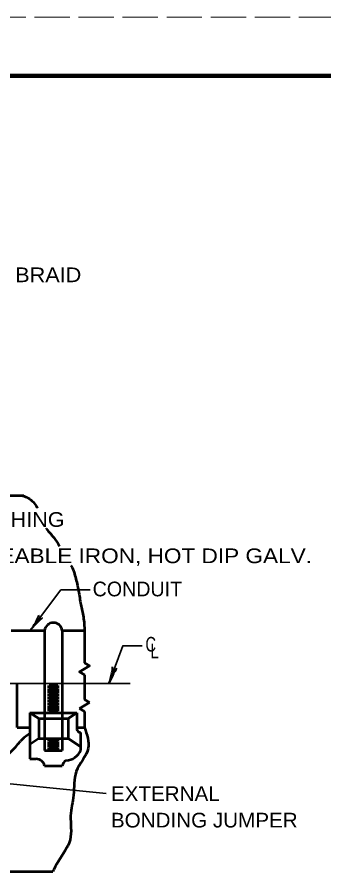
# Model space of a CAD drawing. Extents: x -1 to 679, y 0 to 440.
# Drawn here: x 295.7 to 347.9, y 293.3 to 439.8 of the extents above; entities that cross this region are included whole.
import ezdxf

# ---------------------------------------------------------------- set-up
doc = ezdxf.new("R2010")
doc.units = 0
doc.linetypes.add('LONG_DASHED', pattern=[7.5, 6, -1.5])
doc.layers.add('1', color=7, linetype='Continuous', lineweight=35)
doc.layers.add('61', color=7, linetype='Continuous', lineweight=35)

msp = doc.modelspace()

# ---------------------------------------------------------------- linework, layer by layer
at = {"layer": '1', "lineweight": 53}
for p, q in [((276.934, 358.376), (296.784, 358.376)), ((294.627, 335.376), (300.343, 335.376)), ((300.343, 335.376), (300.343, 314.992)), ((303.343, 335.376), (303.343, 314.992)), ((303.343, 335.376), (307.127, 335.376)), ((307.127, 335.376), (307.127, 329.876)), ((307.127, 327.876), (307.127, 323.626)), ((295.684, 318.876), (295.684, 326.376)), ((300.843, 325.876), (302.843, 325.876)), ((300.843, 325.376), (302.843, 325.376)), ((301.093, 326.126), (302.593, 326.126)), ((301.093, 325.626), (302.593, 325.626)), ((300.843, 324.876), (302.843, 324.876)), ((300.843, 324.376), (302.843, 324.376)), ((300.843, 323.876), (302.843, 323.876)), ((301.093, 325.126), (302.593, 325.126)), ((301.093, 324.626), (302.593, 324.626)), ((301.093, 324.126), (302.593, 324.126)), ((300.843, 323.376), (302.843, 323.376)), ((300.843, 322.876), (302.843, 322.876)), ((300.843, 322.376), (302.843, 322.376)), ((301.093, 323.626), (302.593, 323.626)), ((301.093, 323.126), (302.593, 323.126)), ((301.093, 322.626), (302.593, 322.626)), ((306.261, 322.126), (307.993, 323.126)), ((307.993, 323.126), (307.127, 323.626)), ((297.843, 321.376), (305.843, 321.376)), ((297.843, 321.376), (297.843, 313.53)), ((299.343, 320.402), (297.843, 321.376)), ((300.843, 321.876), (302.843, 321.876)), ((301.093, 322.126), (302.593, 322.126)), ((301.093, 321.626), (302.593, 321.626)), ((304.343, 320.402), (305.843, 321.376)), ((305.843, 321.376), (305.843, 318.876)), ((307.127, 321.626), (306.261, 322.126)), ((307.127, 321.626), (307.127, 318.876)), ((299.343, 320.402), (299.343, 316.992)), ((299.343, 320.402), (304.343, 320.402)), ((304.343, 320.402), (304.343, 316.992)), ((295.684, 318.876), (297.843, 318.876)), ((305.843, 318.876), (307.127, 318.876)), ((306.532, 315.037), (306.532, 318.037)), ((299.343, 316.992), (297.843, 316.018)), ((299.343, 316.992), (304.343, 316.992)), ((300.843, 316.742), (302.843, 316.742)), ((301.093, 316.492), (302.593, 316.492)), ((304.343, 316.992), (306.532, 315.57)), ((300.343, 314.992), (303.343, 314.992)), ((300.843, 316.242), (302.843, 316.242)), ((300.843, 315.742), (302.843, 315.742)), ((300.843, 315.242), (302.843, 315.242)), ((301.093, 315.992), (302.593, 315.992)), ((301.093, 315.492), (302.593, 315.492)), ((297.843, 313.53), (298.904, 313.53)), ((300.343, 312.388), (303.343, 312.388)), ((276.934, 294.376), (301.739, 294.376))]:
    msp.add_line(p, q, dxfattribs=at)
at = {"layer": '1'}
for p, q in [((277.149, 326.376), (301.934, 326.376)), ((301.934, 326.376), (303.684, 326.376)), ((303.684, 326.376), (314.905, 326.376)), ((288.37, 309.942), (310.84, 307.642))]:
    msp.add_line(p, q, dxfattribs=at)
for points in [[(297.941, 335.45), (303.109, 342.343), (308.109, 342.343)], [(311.286, 326.376), (313.63, 332.783), (316.937, 332.783)]]:
    msp.add_lwpolyline(points, dxfattribs=at)
at = {"layer": '1', "lineweight": 53}
msp.add_lwpolyline([(307.127, 327.876), (306.261, 328.376), (307.993, 329.376), (307.127, 329.876)], dxfattribs=at)
for centre, radius, start, end in [((301.843, 335.214), 1.509, 6.16262, 173.83738), ((306.49, 318.705), 0.669, 165.23922, 273.58468), ((273.412, 335.523), 29.679, 300.74714, 320.35337), ((301.606, 311.524), 7.359, 120.75676, 136.54084), ((303.768, 316.279), 3.031, 273.86793, 335.80007), ((298.932, 312.088), 1.443, 12.01693, 91.12043), ((304.495, 312.214), 1.165, 116.66219, 171.42653)]:
    msp.add_arc(centre, radius, start, end, dxfattribs=at)
at = {"layer": '1', "lineweight": 40}
for centre, major_axis, ratio, start_param, end_param in [((298.374, 336.489), (-0.946, -1.522), 0.122415, 0.8963533, 3.1415927), ((298.374, 336.489), (-0.946, -1.522), 0.122415, 0.8963533, 3.1415927), ((298.782, 336.219), (1.194, 1.3), 0.07063, 6.2823074, 8.5597026), ((298.782, 336.219), (1.194, 1.3), 0.07063, 6.2823074, 8.5597026), ((311.402, 327.496), (-0.467, -1.731), 0.122415, 0.8963533, 3.1415927), ((311.87, 327.355), (-0.768, -1.589), 0.07063, 3.1407148, 5.41811)]:
    msp.add_ellipse(centre, major_axis=major_axis, ratio=ratio, start_param=start_param, end_param=end_param, dxfattribs=at)
at = {"layer": '1', "lineweight": 53}
for points in [[(296.636, 358.321), (297.51, 357.971), (299.033, 356.352), (299.068, 356.288)], [(300.611, 352.733), (300.651, 352.686), (301.888, 351.211), (302.87, 349.77)], [(304.827, 346.436), (305.172, 345.831), (305.505, 344.784), (306.076, 342.451), (306.457, 340.071), (306.885, 337.976), (307.123, 335.643), (307.136, 334.821)], [(307.127, 318.876), (307.761, 315.373), (305.719, 311.388), (305.271, 307.354), (304.774, 303.868), (304.674, 299.784), (304.126, 298.439), (301.886, 294.704), (301.736, 294.369)]]:
    msp.add_spline(points, degree=3, dxfattribs=at)
at = {"layer": '61', "linetype": 'LONG_DASHED', "lineweight": 13}
msp.add_line((-1.376, 439.785), (678.644, 439.785), dxfattribs=at)
at = {"layer": '61', "lineweight": 158}
msp.add_lwpolyline([(667.664, 429.785), (28.624, 429.785), (28.624, 9.765)], dxfattribs=at)

# ---------------------------------------------------------------- texts
at = {"layer": '1'}
for s, width, p in [('TINNED COPPER GROUNDING BRAID', 1.1, (240.181, 394.687)), ('INSULATING BUSHING', 1.1, (263.9, 353.04)), ('BODY-MALLEABLE IRON, HOT DIP GALV.', 1.15, (270.435, 346.86)), ('C', 0.75, (317.501, 331.805)), ('L', 0.75, (318.357, 330.663)), ('EXTERNAL', 1.05, (311.623, 306.369)), ('BONDING JUMPER', 1.05, (311.623, 301.869))]:
    msp.add_text(s, height=2.5, dxfattribs=dict(at, width=width)).set_placement(p)
msp.add_text('CONDUIT', height=2.5, dxfattribs=at).set_placement((308.515, 341.214))

doc.saveas('drawing.dxf')
